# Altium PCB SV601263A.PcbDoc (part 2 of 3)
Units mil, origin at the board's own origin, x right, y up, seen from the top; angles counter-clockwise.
Board outline 4070 x 6530 mil, 6 copper layers (Top Layer, Signal Layer 1, Signal Layer 2, Signal Layer 3, Signal Layer 4, Bottom Layer), stack 60.36 mil thick; 305 components, 177 nets, 942 pads, 354 vias.
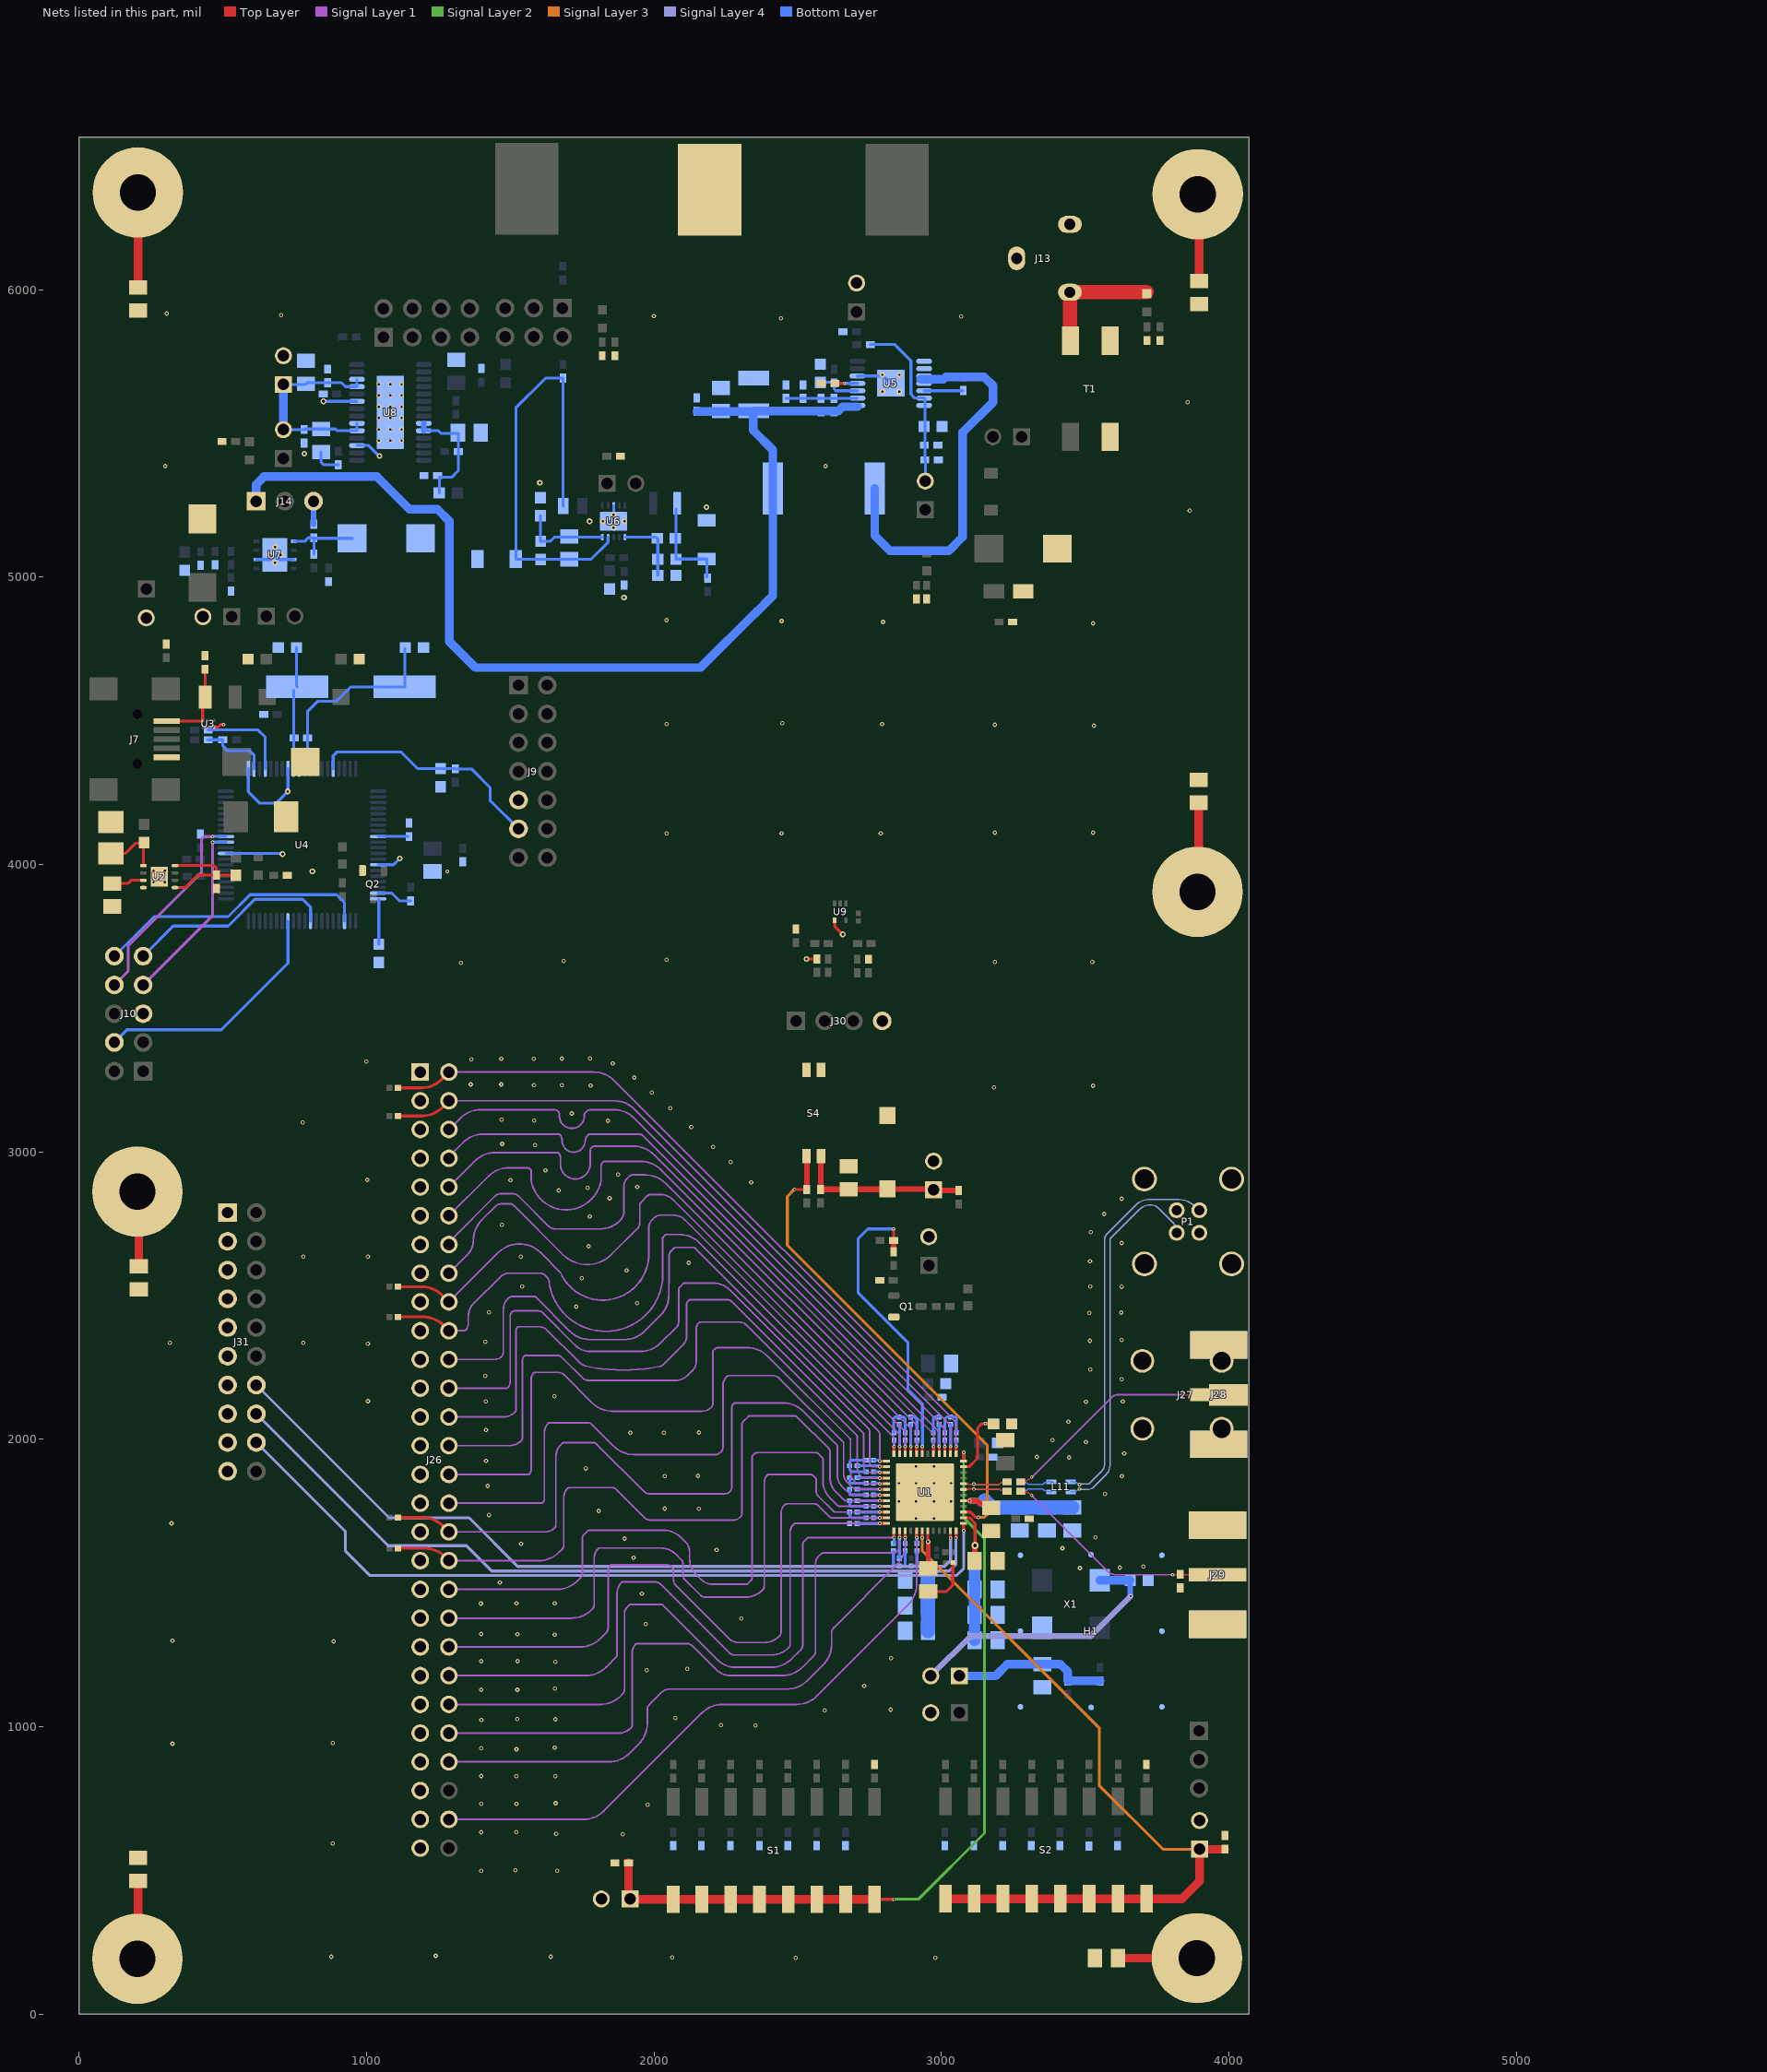
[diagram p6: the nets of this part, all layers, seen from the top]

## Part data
C1 C2 C18 C24 C25 C27 C28 C32 C34 C43 C46 C53 C73 C74 C77 C78 C83: "CAP, CERM, 0.1uF, 16V, +/-10%, X7R, 0402"
C3 C26 C52 C75 C79: "CAP, CERM, 10uF, 10V, +/-10%, X7R, 0805"
C4 C72 C76: "CAP, CERM, 4.7uF, 16V, +/-10%, X7R, 0805"
C5: "CAP, CERM, 0.01uF, 100V, +/-5%, X7R, 0603"
C6: library part GRM188R61C104KA01D, "CAP, CERM, 0.1 µF, 16 V, +/- 10%, X5R, 0603"
C7: "CAP, CERM, 0.1 µF, 16 V, +/- 10%, X5R, 0603"
C8 C9 C10 C11 C12 C13: "CAP, CERM, 4700 pF, 100 V, +/- 10%, X7R, 0805"
C14: "CAP, TA, 22uF, 20V, +/-20%, 0.7 ohm, SMD"
C15: "CAP, CERM, 1 µF, 6.3 V, +/- 20%, X5R, 0402"
C16: "CAP, TA, 2.2uF, 25V, +/-10%, 3.8 ohm, SMD"
C17: "CAP, CERM, 0.01uF, 100V, +/-10%, X7R, 0805"
C19 C21: "CAP, CERM, 20 pF, 100 V, +/- 5%, C0G/NP0, 0603"
C20: "CAP, CERM, 220 pF, 50 V, +/- 1%, C0G/NP0, 0603"
C22: "CAP, CERM, 200 pF, 50 V, +/- 5%, C0G/NP0, 0402"
C23: "CAP, CERM, 2200 pF, 50 V, +/- 10%, X7R, 0603"
C29: "CAP, CERM, 0.47uF, 16V, +/-10%, X7R, 0603"
C30 C31: "CAP, CERM, 10pF, 50V, +/-5%, C0G/NP0, 0402"
C33 C58: library part C1608X7R1C105K080AC, "CAP, CERM, 1 µF, 16 V, +/- 10%, X7R, 0603"
C35 C36 C37 C38 C39 C40 C41 C42 C47 C48 C49 C50 C56 C62: "CAP, CERM, 4.7 µF, 16 V, +/- 10%, X7R, AEC-Q200 Grade 1, 0805"
C44 C70 C71: "CAP, TA, 22uF, 25V, +/-20%, 0.7 ohm, SMD"
C45: "CAP, TA, 2.2uF, 25V, +/-10%, 6.3 ohm, SMD"
C51: "CAP, CERM, 47uF, 16V, +/-20%, X5R, 1210"
C54 C64: "CAP, CERM, 0.047 µF, 16 V, +/- 10%, X7R, 0402"
C55 C63: "CAP, CERM, 0.47 µF, 25 V, +/- 10%, X7R, 0603"
C57: "CAP, CERM, 3300pF, 50V, +/-10%, X7R, 0402"
C59 C68: "CAP, CERM, 10 µF, 25 V, +/- 20%, X5R, 0603"
C60: library part 06035A330JAT2A, "CAP, CERM, 33 pF, 50 V, +/- 5%, C0G/NP0, 0603"
C61 C66: "CAP, CERM, 22 µF, 35 V, +/- 20%, X5R, 1206_190"
C65: "CAP, CERM, 33 pF, 50 V, +/- 5%, C0G/NP0, 0603"
C67: library part C1005X7R1H104K050BB, "CAP, CERM, 0.1 µF, 50 V, +/- 10%, X7R, 0402"
C69: "CAP, CERM, 0.47 µF, 16 V, +/- 10%, X5R, 0402"
C80 C81: library part GCM155R71H104KE02D, "CAP, CERM, 0.1 µF, 50 V, +/- 10%, X7R, AEC-Q200 Grade 1, 0402"
C82: "CAP, CERM, 0.33 µF, 10 V, +/- 10%, X5R, 0402"
C84: "CAP, CERM, 0.15 µF, 10 V, +/- 10%, X5R, 0402"
C85 C86: "CAP, CERM, 4.7pF, 25V, +/-5%, C0G/NP0, 0402"
D1 D2 D3 D4 D5 D8: "LED, Green, SMD"
D6: "LED, Orange, SMD"
D7: "Diode, Zener, 7.5V, 550mW, SMB"
D9: "Diode, Schottky, 40V, 1A, SOD-123"
F1: "Fuse, 7 A, 24 V, SMD"
H1: "EMI SHIELD, 13.66 x 12.70 mm, SMT"
J1 J2 J3 J5 J6 J8 J11 J12 J15 J16 J18 J19 J20 J22 J32: "Header, 100mil, 2x1, Gold, TH"
J4 J14: "Header, 100mil, 3x1, Gold, TH"
J7: "Connector, Receptacle, Mini-USB Type B, R/A, Top Mount SMT"
J9: "Header, 100mil, 7x2, Tin, TH"
J10: "Header, 100mil, 5x2, Tin, TH"
J13: "Connector, DC Jack 2.1X5.5 mm, TH"
J17: "Header, 100mil, 3x2, Gold, TH"
J21: "Header, 100mil, 4x2, Gold, TH"
J23 J25: "Standard Banana Jack, Insulated, Red"
J24: "Standard Banana Jack, Insulated, Black"
J26: "Header, 100mil, 28x2, Gold, TH"
J27: "Connector, RF, 50 Ohm, R/A, TH"
J28 J29: "Connector, End launch SMA, 50 ohm, SMT"
J30: "Header (friction lock), 100mil, 4x1, Gold, TH"
J31: "Header, 100mil, 10x2, TH"
L1 L7 L9: "Ferrite Bead, 1000 ohm @ 100 MHz, 0.35 A, 0402"
L2: "Ferrite Bead, 60 ohm @ 100MHz, 0.8A, 0603"
L6: "Inductor, Shielded Drum Core, Ferrite, 4.7 µH, 4.2 A, 0.02 ohm, SMD"
L8: "Inductor, Shielded, Ferrite, 2.2 µH, 1.23 A, 0.084 ohm, SMD"
L10: "Inductor, Multilayer, Ferrite, 3.3 µH, 0.6 A, 0.143 ohm, SMD"
L11: "Coupled inductor, 0.28 A, 0.41 ohm, +/- 25%, SMD"
LBL?: library part THT-13-457-10, "Thermal Transfer Printable Labels, 1.250\" W x 0.250\" H - 10,000 per roll"
Logo1: library part TI_Logo, "Texas Instrument Corporate Signature"
Logo2: library part FCC_disclaimer, "FCC_disclaimer"
Logo?: library part Pb-Free
M1 M2 M3 M4 M5 M6: "TEST POINT.  No entry in BOM."
P1: "HSD Right Angle Plug for PCB, TH"
Q1 Q2: "MOSFET, N-CH, 50 V, 0.22 A, SOT-23"
R1 R8 R22 R30 R53 R56 R64 R94 R99 R105 R110 R113 R118 R119: "RES, 0 ohm, 5%, 0.063W, 0402"
R2 R9 R21 R29: "RES, 107k ohm, 1%, 0.063W, 0402"
R3 R10 R20 R28: "RES, 255k ohm, 1%, 0.063W, 0402"
R4 R11: "RES, 100k ohm, 1%, 0.1W, 0402"
R5 R12: "RES, 105k ohm, 1%, 0.063W, 0402"
R6 R13 R17 R25: "RES, 102k ohm, 1%, 0.063W, 0402"
R7 R14 R16 R24: "RES, 17.8k ohm, 1%, 0.063W, 0402"
R15 R23 R31 R32 R33 R93 R97 R100 R103 R107: "RES, 10.0 k, 1%, 0.063 W, 0402"
R18 R26: "RES, 75k ohm, 5%, 0.063W, 0402"
R19 R27: "RES, 140k ohm, 1%, 0.063W, 0402"
R34 R37 R39 R121 R122 R123 R124 R125 R126: "RES, 0, 5%, 0.05 W, 0201"
R35 R36 R38 R40 R41 R42 R43 R44 R45 R46 R47 R49 R50 R51 R52 R54 R55 R57 R58 R59 R60 R61 R62 R63 R65 R66 R67 R68: "RES, 49.9, 1%, 0.05 W, 0201"
R48 R115 R116: "RES, 4.7k ohm, 5%, 0.063W, 0402"
R69: "RES, 470 ohm, 5%, 0.063W, 0402"
R70 R71 R75 R76: "RES, 2.4 k, 5%, 0.063 W, 0402"
R72 R73: "RES, 220, 5%, 0.063 W, 0402"
R74 R77: "RES, 180, 5%, 0.063 W, 0402"
R78 R92 R109 R112: "RES, 100k ohm, 5%, 0.063W, 0402"
R79 R111 R114: "RES, 0, 5%, 0.1 W, 0603"
R80 R81: "RES, 33 ohm, 5%, 0.063W, 0402"
R82: "RES, 1.5 k, 5%, 0.063 W, 0402"
R83 R86: "RES, 33k ohm, 5%, 0.063W, 0402"
R84: "RES, 1.2 M, 5%, 0.1 W, 0603"
R85: library part CRCW04020000Z0ED, "RES, 0, 5%, 0.063 W, 0402"
R87: "RES, 200 ohm, 5%, 0.063W, 0402"
R88 R89: "RES, 0, 5%, 0.063 W, 0402"
R90: "RES, 124k ohm, 1%, 0.063W, 0402"
R91: "RES, 22.1k ohm, 1%, 0.063W, 0402"
R95 R108: "RES, 3.24k ohm, 1%, 0.063W, 0402"
R96: "RES, 806 k, 0.1%, 0.125 W, 0805"
R98 R104: "RES, 180 k, 0.1%, 0.1 W, 0603"
R101: library part ERJ-3EKF3603V, "RES, 360 k, 1%, 0.1 W, AEC-Q200 Grade 0, 0603"
R102: library part CRCW040210K0FKED, "RES, 10.0 k, 1%, 0.063 W, 0402"
R106: "RES, 29.4 k, 1%, 0.063 W, 0402"
R117: "RES, 49.9 ohm, 1%, 0.063W, 0402"
S1 S2: "Switch, Slide, SPST 8 poles, SMT"
S3 S5: "Switch, Normally open, 2.3N force, 200k operations, SMD"
S4: "Switch, SPST, 2 Pos, 25mA, 24VDC, SMD"
SH-J11 SH-J12 SH-J19 SH-J22: "Shunt, 100mil, Gold plated, Black"
T1: "Common Mode Filter for Power Line"
U1: "5 - 96 MHz 24-bit Color FPD-Link III Serializer with Bidirectional Control Channel, RHS0048A"
U2: "Single Output High PSRR LDO, 500 mA, Fixed 3.3 V Output, 2.7 to 6.5 V Input, with Low IQ, 8-pin SON (DRB), -40 to 125 degC, Green (RoHS & no Sb/Br)"
U3: "4-CHANNEL ESD-PROTECTION ARRAY FOR HIGH-SPEED DATA INTERFACES, DRY006A"
U4: "Mixed Signal MicroController, PN0080A"
U5: "4.5V to 18V Input, 2-A Synchronous Step-Down SWIFT™ Converter, PWP0014E"
U6: "2.25MHz 2x800mA Dual Step Down Converter In Small 3x3mm QFN Package, DRC0010J"
U7: "1A Low Dropout Adjustable Regulator, 8-pin LLP, Pb-Free"
U8: "Dual Output LDO, 1 A, Fixed 1.8, 3.3 V Output, 2.7 to 10 V Input, 28-pin HTSSOP (PWP), -40 to 125 degC, Green (RoHS & no Sb/Br)"
U9: "Low-Capacitance + / - 15 kV ESD-Protection Array for High-Speed Data Interfaces, 2 Channels, -40 to +85 degC, 5-pin SOT (DRL), Green (RoHS & no Sb/Br)"
X1: "OSC, 96 MHz, 3.3 Vdc, SMD"
Y1: "Crystal, 24.000MHz, 20pF, SMD"
ZZ1: library part AssemblyNote
ZZ2 ZZ3 ZZ4 ZZ5: library part AssemblyNoteLabel
ZZ6 ZZ7 ZZ8 ZZ9: library part "Assembly Note"

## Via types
v1: diameter 15, hole 7.5, Top Layer to Bottom Layer, 187 vias
v2: diameter 12, hole 6, Top Layer to Bottom Layer, 96 vias
v3: diameter 19.68, hole 7.87, Top Layer to Bottom Layer, 28 vias
v4: diameter 15.75, hole 7.87, Top Layer to Bottom Layer, 18 vias
v5: diameter 20, hole 10, Top Layer to Bottom Layer, 14 vias
v6: diameter 25, hole 12, Top Layer to Bottom Layer, 9 vias
v7: diameter 16, hole 8, Top Layer to Bottom Layer, 2 vias

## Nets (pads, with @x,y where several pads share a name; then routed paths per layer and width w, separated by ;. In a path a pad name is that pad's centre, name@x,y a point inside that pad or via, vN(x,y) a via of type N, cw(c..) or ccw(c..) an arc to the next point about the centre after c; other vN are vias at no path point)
5V_LDO: J14.3 R105.2 | length 79.4
  Bottom Layer w20: R105.2@816,5184.62 J14.3@816,5264
5V_SW: C30.2 C51.1 C52.1 C53.2 J14.1 L6.1 R90.1 U5.1 | length 3735.7
  Bottom Layer w30: J14.1@616,5264 616,5322 644,5350 1036,5350 1150,5236 1247,5236 1288,5195 1288,4776.37 1379.37,4685 2162,4685 2358,4881 ; C53.2@2149,5576.38 2345.46,5576.38 2345.46,5510.54 2413.83,5442.17 L6.1@2413.83,5308 2413.83,4934.83 2351,4872 ; C51.1@2347,5577.91 2641.54,5577.91 2656.58,5592.96 U5.1@2707.86,5592.96
12V_IN_B4JUMP: D1.2 J13.1 T1.2 | length 435.1
  Top Layer w50: T1.2@3449.1,5822.32 cw(c3454.18,5827.4) 3447,5827.4 J13.1@3447,5990.89 D1.2@3713,5990.89
CAPHS_12: C39.1 C40.1 C41.1 C42.1 U1.17 | length 466.3
  Top Layer w10: U1.17@3076.86,1786.47 v2(3098.53,1786.47)
  Top Layer w20: v2(3098.53,1786.47) 3123.53,1786.47 3133,1777 C42.1@3173,1777
  Bottom Layer w20: v2(3098.53,1786.47) 3151.53,1786.47
  Bottom Layer w50: 3151.53,1786.47 3175,1763 C41.1@3273,1763 C40.1@3367,1763 C39.1@3455,1763
CAPL12: C35.1 C36.1 C37.1 C38.1 U1.7 | length 447.1
  Top Layer w10: v7@2952.84,1644 U1.7@2952.84,1682.14
  Top Layer w15: C38.1@2954,1545 v7(2954,1644)
  Bottom Layer w15: C37.1@2954,1511 v7(2954,1644)
  Bottom Layer w50: C36.1@2954,1334 C35.1@2954,1422 C37.1@2954,1511
CAPP_12: C47.1 C48.1 C49.1 C50.1 U1.14 | length 507.2
  Top Layer w10: U1.14@3076.86,1727.42 3097.58,1727.42 3117,1708 v6(3117,1631)
  Top Layer w20: C50.1@3116,1577 v6@3116,1630
  Bottom Layer w20: 3116,1577 v6@3116,1630
  Bottom Layer w40: C47.1@3116,1301 3116,1577
CMF: C6.1 C7.1 U1.23 | length 257.4
  Top Layer w10: U1.23@3076.86,1904.58 3096.58,1904.58 3126,1934 3126,2040 3140,2054 C6.1@3181.5,2054
  Bottom Layer w10: v2(3153,2055) ccw(c3155.41,2057.41) 3155.41,2054 C7.1@3181.5,2054
DE: J26.54 R68.1 U1.5 | length 2179.8
  Top Layer w10: U1.5@2913.47,1682.14 2913.47,1659.27 ccw(c2915.27,1659.27) v2(2914,1658)
  Signal Layer 1 w6: J26.54@1287,678 1755.58,678 ccw(c1755.58,778) 1826.29,707.29 2167.71,1048.71 cw(c2238.42,978) 2238.42,1078 2496.58,1078 ccw(c2496.58,1178) 2567.29,1107.29 2884.71,1424.71 ccw(c2814,1495.42) 2914,1495.42 v2(2914,1658)
  Bottom Layer w10: v2(2914,1658) cw(c2911.59,1655.59) 2915,1655.59 R68.1@2915,1637.99
DIN0/R0: J26.2 R35.2 R121.2 U1.25 | length 2588.6
  Top Layer w10: R121.2@1109.96,3223 1190.58,3223 ccw(c1190.58,3323) 1261.29,3252.29 J26.2@1287,3278 ; U1.25@3051.27,1949.86 v2@3051.27,1974.73
  Signal Layer 1 w6: J26.2@1287,3278 1790.57,3278 cw(c1790.57,3178) 1861.28,3248.71 3041.11,2068.89 cw(c3017.22,2045) 3051,2045 v2(3051,1975)
  Bottom Layer w10: v2@3052,1976 R35.2@3052,1997.01
DIN1/R1: J26.4 R36.1 R122.2 U1.26 | length 2577.2
  Top Layer w10: R122.2@1109.96,3125 1192.58,3125 ccw(c1192.58,3225) 1263.29,3154.29 J26.4@1287,3178 ; U1.26@3031.58,1949.86 v2@3031.58,1974.58
  Signal Layer 1 w6: J26.4@1287,3178 1861.58,3178 cw(c1861.58,3078) 1932.29,3148.71 3021,2060 cw(c2994.44,2033.44) 3032,2033.44 v2(3032,1975)
  Bottom Layer w10: v2(3032,1975) R36.1@3032,2052.01
DIN2/R2: J26.6 R38.1 U1.27 | length 2388.1
  Top Layer w10: v2@3011.9,1974.9 U1.27@3011.9,1949.86 U1.27@3012,1949.96
  Signal Layer 1 w6: J26.6@1287,3078 1326.71,3117.71 cw(c1397.42,3047) 1397.42,3147 1652.51,3147 cw(c1652.51,3126.51) 1667,3141 cw(c1657.34,3131.34) 1671,3131.34 1671,3123 ccw(c1714.57,3125.65) 1758,3121.27 ; 1758,3122 1758,3129 cw(c1767.66,3129) 1760.83,3135.83 1766,3141 cw(c1780.49,3126.51) 1780.49,3147 1860.58,3147 cw(c1860.58,3047) 1931.29,3117.71 3004,2045 cw(c2984.69,2025.69) 3012,2025.69 v2(3012,1975)
  Bottom Layer w10: v2(3012,1975) R38.1@3012,1997.01
DIN3/R3: J26.8 R40.1 U1.28 | length 2396.4
  Top Layer w10: U1.28@2992.21,1949.86 v2@2992.21,1974.79
  Signal Layer 1 w6: J26.8@1287,2978 cw(c1301.49,2978) 1291.23,2988.23 1335.71,3032.71 cw(c1406.42,2962) 1406.42,3062 1670,3062 cw(c1670,3059.59) 1671.71,3061.29 cw(c1649.27,3038.86) 1681,3038.86 1681,3032 ; 1681,3034 ccw(c1720.57,3038.86) 1760,3033 cw(c1796.21,3033) 1770.61,3058.61 1773,3061 cw(c1775.41,3058.59) 1775.41,3062 1950.34,3062 cw(c1950.34,3048.34) 1960,3058 2987,2031 cw(c2974.93,2018.93) 2992,2018.93 v2(2992,1975)
  Bottom Layer w10: v2(2992,1975) R40.1@2992,2052.01
DIN4/R4: J26.10 R41.1 U1.29 | length 2379
  Top Layer w10: U1.29@2972.53,1949.86 v2@2972.53,1974.53
  Signal Layer 1 w6: J26.10@1287,2878 1377.71,2968.71 cw(c1448.42,2898) 1448.42,2998 1667,2998 cw(c1647.69,2978.69) 1675,2978.69 1675,2953 ccw(c1726.5,2957.71) 1778,2953 1778,3002 cw(c1797.31,3002) 1783.66,3015.66 1784.88,3016.88 cw(c1790,3011.76) 1790,3019 cw(c1792.41,3016.59) 1792.41,3020 1929.58,3020 cw(c1929.58,2920) 2000.29,2990.71 2967,2024 cw(c2952.51,2009.51) 2973,2009.51 v2(2973,1975)
  Bottom Layer w10: v2@2972,1976 R41.1@2972,1997.01
DIN5/R5: J26.12 R42.1 U1.32 | length 2387.4
  Top Layer w10: U1.32@2913.47,1949.86 v2@2913.47,1974.47
  Signal Layer 1 w6: J26.12@1287,2778 1424.71,2915.71 cw(c1495.42,2845) 1495.42,2945 1556.51,2945 cw(c1556.51,2924.51) 1571,2939 cw(c1566.17,2934.17) 1573,2934.17 1573,2900.41 ccw(c1694.5,2921.72) 1816,2900.41 1816,2947.27 cw(c1841.9,2947.27) 1823.59,2965.59 cw(c1827,2962.17) 1827,2967 1954.58,2967 cw(c1954.58,2867) 2025.29,2937.71 2911,2052 cw(c2903.76,2044.76) 2914,2044.76 v2(2914,1975)
  Bottom Layer w10: v2@2915,1976 R42.1@2915,1997.01
DIN6/R6: J26.14 R43.1 U1.33 | length 2396.1
  Top Layer w10: U1.33@2893.79,1949.86 v2@2893.79,1974.79
  Signal Layer 1 w6: J26.14@1287,2678 cw(c1306.31,2678) 1292.66,2691.66 1448,2847 cw(c1467.31,2827.69) 1467.31,2855 1504,2855 cw(c1504,2813.96) 1533.02,2842.98 1635.51,2740.49 ccw(c1656,2760.97) 1656,2732 1811.58,2732 ccw(c1811.58,2832) 1882.29,2761.29 ccw(c1849.19,2794.39) 1896,2794.39 1896,2883 cw(c1929.8,2883) 1905.9,2906.9 1914.76,2915.76 cw(c1925,2905.51) 1925,2920 1969.58,2920 cw(c1969.58,2820) 2040.29,2890.71 2890.46,2040.54 cw(c2881.93,2032) 2894,2032 v2(2894,1975)
  Bottom Layer w10: R43.1@2893,2052.01 2893.27,2051.74 v2@2893.27,1975.73
DIN7/R7: J26.16 R44.1 U1.34 | length 2378.8
  Top Layer w10: U1.34@2874.1,1949.86 v2@2874.1,1974.9
  Signal Layer 1 w6: J26.16@1287,2578 1351.08,2642.08 ccw(c1300.59,2692.58) 1372,2692.58 cw(c1472,2692.58) 1401.29,2763.29 1448.1,2810.1 cw(c1472,2786.2) 1472,2820 1497,2820 cw(c1497,2798.27) 1512.36,2813.64 1683,2643 ccw(c1767.5,2727.5) 1852,2643 1942.51,2733.51 ccw(c1922.03,2754) 1951,2754 1951,2815 cw(c1965.49,2815) 1955.23,2825.23 1977,2847 cw(c1989.07,2834.93) 1989.07,2852 2021,2852 cw(c2021,2784.4) 2068.8,2832.2 2871.17,2029.83 cw(c2864.32,2022.99) 2874,2022.99 v2(2874,1975)
  Bottom Layer w10: v2(2874,1975) R44.1@2874,1997.01
DIN8/G0: J26.18 R45.1 R123.2 U1.35 | length 2580.9
  Top Layer w10: R123.2@1109.96,2531 1192.58,2531 cw(c1192.58,2431) 1263.29,2501.71 J26.18@1287,2478 ; U1.35@2854.42,1949.86 v2@2854.42,1974.42
  Signal Layer 1 w6: J26.18@1287,2478 1458.6,2649.6 cw(c1532,2576.21) 1605.4,2649.6 1675,2580 ccw(c1821.82,2644.81) 1982,2635 1982,2735 cw(c2023.04,2735) 1994.02,2764.02 2002,2772 cw(c2021.31,2752.69) 2021.31,2780 2068,2780 cw(c2068,2724.47) 2107.26,2763.74 2850.05,2020.95 cw(c2838.1,2009) 2855,2009 v2(2855,1975)
  Bottom Layer w10: v2@2854.73,1975.27 2854.73,2051.74 R45.1@2855,2052.01
DIN9/G1: J26.20 R46.1 R124.2 U1.36 | length 2590.4
  Top Layer w10: R124.2@1109.96,2426 1197.58,2426 cw(c1197.58,2326) 1268.29,2396.71 J26.20@1287,2378 ; U1.36@2834.73,1949.86 v2@2834.73,1974.73
  Signal Layer 1 w6: J26.20@1304.07,2385.07 cw(c1287,2402.14) J26.20@1287,2378 1338.76,2378 ccw(c1338.76,2388.24) 1346,2381 ccw(c1326.69,2400.31) 1354,2400.31 1354,2426 cw(c1421.6,2426) 1373.8,2473.8 1465,2564 cw(c1497.77,2532.92) 1495,2578 1605,2578 cw(c1605,2556.27) 1620.36,2571.64 1628,2564 cw(c1607.48,2543.48) 1636.5,2543.48 1636.5,2537.6 ccw(c1831.95,2574.79) 2030,2555.79 2030,2697 cw(c2042.07,2697) 2033.54,2705.54 2038.88,2710.88 cw(c2044,2705.76) 2044,2713 2087.58,2713 cw(c2087.58,2613) 2158.29,2683.71 2832,2010 cw(c2824.76,2002.76) 2835,2002.76 v2(2835,1975)
  Bottom Layer w10: v2(2835,1975) R46.1@2835,1997.01
DIN10/G2: J26.22 R47.1 U1.37 | length 2389.6
  Top Layer w10: v2@2786.27,1924.27 U1.37@2809.14,1924.27
  Signal Layer 1 w6: J26.22@1287,2278 1447.27,2278 ccw(c1447.27,2308.73) 1469,2287 ccw(c1452.1,2303.9) 1476,2303.9 1476,2452 cw(c1526.7,2452) 1490.85,2487.85 1496,2493 cw(c1505.66,2483.34) 1505.66,2497 1583,2497 cw(c1583,2487.34) 1589.83,2494.17 1707.71,2376.29 ccw(c1778.42,2447) 1778.42,2347 1896.58,2347 ccw(c1896.58,2447) 1967.29,2376.29 2022.71,2431.71 ccw(c1952,2502.42) 2052,2502.42 2052,2543 ccw(c2049.59,2545.41) 2053,2545.41 2053,2640 cw(c2074.73,2640) 2059.36,2655.36 2066,2662 cw(c2080.49,2647.51) 2080.49,2668 2137,2668 cw(c2137,2658.34) 2143.83,2665.17 2780,2029 cw(c2765.51,2014.51) 2786,2014.51 v2(2786,1924)
  Bottom Layer w10: R47.1@2763.99,1928 2776.34,1928 cw(c2776.34,1914.34) v2(2786,1924)
DIN11/G3: J26.24 R49.1 U1.38 | length 2402
  Top Layer w10: v2(2786,1905) ccw(c2787.01,1906.01) 2787.01,1904.58 U1.38@2809.14,1904.58
  Signal Layer 1 w6: J26.24@1287,2178 1488.59,2178 ccw(c1488.59,2181.41) 1491,2179 ccw(c1469.27,2200.73) 1500,2200.73 1500,2428.51 cw(c1520.49,2428.51) 1506,2443 cw(c1515.66,2433.34) 1515.66,2447 1598,2447 cw(c1598,2425.27) 1613.36,2440.64 1727,2327 ccw(c1777.7,2377.7) 1777.7,2306 1952.58,2306 ccw(c1952.58,2406) 2023.29,2335.29 2079,2391 ccw(c2062.1,2407.9) 2086,2407.9 2086,2522 cw(c2095.66,2522) 2088.83,2528.83 2102,2542 cw(c2106.83,2537.17) 2106.83,2544 2205,2544 cw(c2205,2459.5) 2264.75,2519.25 2746,2038 cw(c2736.34,2028.34) 2750,2028.34 2750,1921.07 ccw(c2767.07,1921.07) 2755,1909 ccw(c2764.66,1918.66) 2764.66,1905 v2(2786,1905)
  Bottom Layer w10: R49.1@2706.99,1908 2778.76,1908 cw(c2778.76,1897.76) v2@2781,1907.75
DIN12/G4: J26.26 R50.1 U1.39 | length 2384.7
  Top Layer w10: v2@2786.1,1884.9 U1.39@2809.14,1884.9
  Signal Layer 1 w6: J26.26@1287,2078 1475.96,2078 ccw(c1475.96,2136.04) 1517,2095 ccw(c1509.76,2102.24) 1520,2102.24 1520,2377.93 cw(c1537.07,2377.93) 1525,2390 cw(c1529.83,2385.17) 1529.83,2392 1602,2392 cw(c1602,2358.2) 1625.9,2382.1 1738.5,2269.5 ccw(c1779.33,2310.62) 1767,2254 ccw(c1893.1,2859.06) 2019.2,2254 ccw(c2019.2,2270.41) 2030.81,2258.81 2101,2329 ccw(c2069.62,2360.38) 2114,2360.38 2114,2471 cw(c2126.07,2471) 2117.54,2479.54 2122,2484 cw(c2126.83,2479.17) 2126.83,2486 2256,2486 cw(c2256,2466.69) 2269.66,2480.34 2729,2021 cw(c2726.59,2018.59) 2730,2018.59 2730,1908 ccw(c2758.95,1908) 2738.48,1887.53 2738.89,1887.12 ccw(c2744,1892.22) 2744,1885 v2(2786,1885)
  Bottom Layer w10: R50.1@2763.99,1888 2778.76,1888 cw(c2778.76,1877.76) v2(2786,1885)
DIN13/G5: J26.28 R51.1 U1.40 | length 2385
  Top Layer w10: v2@2786.21,1865.21 U1.40@2809.14,1865.21
  Signal Layer 1 w6: J26.28@1287,1978 1496.96,1978 ccw(c1496.96,2036.04) 1538,1995 ccw(c1525.93,2007.07) 1543,2007.07 1543,2275.51 cw(c1563.49,2275.51) 1549,2290 cw(c1553.83,2285.17) 1553.83,2292 1665,2292 cw(c1665,2273.31) 1678.21,2286.53 1685.36,2279.38 1754,2212 ccw(c1770.9,2228.9) 1770.9,2205 2072,2205 ccw(c2072,2272.6) 2119.8,2224.8 2134,2239 ccw(c2102.62,2270.38) 2147,2270.38 2147,2384 cw(c2175.97,2384) 2155.49,2404.49 2156,2405 cw(c2163.24,2397.76) 2163.24,2408 2299,2408 cw(c2299,2379.03) 2319.49,2399.51 2706,2013 cw(c2703.59,2010.59) 2707,2010.59 2707,1905.21 ccw(c2758.21,1905.21) 2722,1869 ccw(c2731.66,1878.66) 2731.66,1865 v2(2786,1865)
  Bottom Layer w10: R51.1@2706.99,1867 2781.17,1867 cw(c2781.17,1860.17) v2(2786,1865)
DIN14/G6: J26.30 R52.1 U1.41 | length 2403.5
  Top Layer w10: v2(2786,1845) cw(c2787.27,1843.73) 2787.27,1845.53 U1.41@2809.14,1845.53
  Signal Layer 1 w6: J26.30@1287,1878 1563.59,1878 ccw(c1563.59,1881.41) 1566,1879 ccw(c1549.1,1895.9) 1573,1895.9 1573,2210.69 cw(c1600.31,2210.69) 1581,2230 cw(c1588.24,2222.76) 1588.24,2233 1667,2233 cw(c1667,2204.03) 1687.49,2224.51 1784.71,2127.29 ccw(c1855.42,2198) 1855.42,2098 2167.62,2098 ccw(c2167.62,2142.38) 2199,2111 ccw(c2184.51,2125.49) 2205,2125.49 2205,2306 cw(c2209.83,2306) 2206.41,2309.41 2212,2315 cw(c2221.66,2305.34) 2221.66,2319 2324.58,2319 cw(c2324.58,2219) 2395.29,2289.71 2682,2003 cw(c2677.17,1998.17) 2684,1998.17 2684,1884 ccw(c2722.63,1884) 2695.31,1856.69 2703,1849 ccw(c2712.66,1858.66) 2712.66,1845 v2(2786,1845)
  Bottom Layer w10: R52.1@2763.99,1847 2781.17,1847 cw(c2781.17,1840.17) v2(2786,1845)
DIN15/G7: J26.32 R54.1 U1.42 | length 2389.1
  Top Layer w10: v2@2786.16,1825.84 U1.42@2809.14,1825.84
  Signal Layer 1 w6: J26.32@1287,1778 1609.17,1778 ccw(c1609.17,1784.83) 1614,1780 ccw(c1601.93,1792.07) 1619,1792.07 1619,2023.2 cw(c1666.8,2023.2) 1633,2057 cw(c1635.41,2054.59) 1635.41,2058 1768,2058 cw(c1768,2033.86) 1785.07,2050.93 1860,1976 ccw(c1930.01,2046.01) 1930.01,1947 2211.27,1947 ccw(c2211.27,1977.73) 2233,1956 ccw(c2216.1,1972.9) 2240,1972.9 2240,2186.62 cw(c2284.38,2186.62) 2253,2218 cw(c2262.66,2208.34) 2262.66,2222 2412,2222 cw(c2412,2185.79) 2437.61,2211.39 2657,1992 cw(c2649.76,1984.76) 2660,1984.76 2660,1880 ccw(c2701.04,1880) 2672.02,1850.98 2686,1837 ccw(c2712.56,1863.56) 2712.56,1826 v2(2786,1826)
  Bottom Layer w10: R54.1@2706.99,1827 2783.59,1827 cw(c2783.59,1823.59) v2(2786,1826)
DIN16/B0: J26.34 R55.1 R125.2 U1.43 | length 2589
  Top Layer w10: R125.2@1109.96,1728 1195.58,1728 cw(c1195.58,1628) 1266.29,1698.71 J26.34@1287,1678 ; v2@2786.16,1806.16 U1.43@2809.14,1806.16
  Signal Layer 1 w6: J26.34@1287,1678 1621.2,1678 ccw(c1621.2,1725.8) 1655,1692 ccw(c1645.34,1701.66) 1659,1701.66 1659,1941 cw(c1714.53,1941) 1675.26,1980.26 1682,1987 cw(c1684.41,1984.59) 1684.41,1988 1792,1988 cw(c1792,1978.34) 1798.83,1985.17 1967,1817 ccw(c1981.49,1831.49) 1981.49,1811 2247.1,1811 ccw(c2247.1,1834.9) 2264,1818 ccw(c2247.1,1834.9) 2271,1834.9 2271,2112 cw(c2285.49,2112) 2275.23,2122.23 2277,2124 cw(c2284.24,2116.76) 2284.24,2127 2448.58,2127 cw(c2448.58,2027) 2519.29,2097.71 2637,1980 cw(c2634.59,1977.59) 2638,1977.59 2638,1875 ccw(c2691.11,1875) 2653.55,1837.45 2682,1809 ccw(c2689.24,1816.24) 2689.24,1806 v2(2786,1806)
  Bottom Layer w10: R55.1@2763.99,1807 2783.59,1807 cw(c2783.59,1803.59) v2(2786,1806)
DIN17/B1: J26.36 R57.1 R126.2 U1.44 | length 2573.9
  Top Layer w10: R126.2@1109.96,1621 1202.58,1621 cw(c1202.58,1521) 1273.29,1591.71 J26.36@1287,1578 ; v2(2786,1787) ccw(c2787.27,1788.27) 2787.27,1786.47 U1.44@2809.14,1786.47
  Signal Layer 1 w6: J26.36@1287,1578 1599.58,1578 ccw(c1599.58,1678) 1670.29,1607.29 1680,1617 ccw(c1665.51,1631.49) 1686,1631.49 1686,1797.62 cw(c1730.38,1797.62) 1699,1829 cw(c1706.24,1821.76) 1706.24,1832 1855,1832 cw(c1855,1812.69) 1868.66,1826.34 1967,1728 ccw(c1988.73,1749.73) 1988.73,1719 2274.44,1719 ccw(c2274.44,1756.56) 2301,1730 ccw(c2288.93,1742.07) 2306,1742.07 2306,2051 cw(c2320.49,2051) 2310.23,2061.23 2329,2080 cw(c2333.83,2075.17) 2333.83,2082 2486,2082 cw(c2486,2062.69) 2499.66,2076.34 2608,1968 cw(c2598.34,1958.34) 2612,1958.34 2612,1869 ccw(c2686.84,1869) 2633.92,1816.08 2660,1790 ccw(c2667.24,1797.24) 2667.24,1787 v2(2786,1787)
  Bottom Layer w10: R57.1@2706.99,1787 v2(2786,1787)
DIN18/B2: J26.38 R58.1 U1.45 | length 2392.6
  Top Layer w10: v2@2786.21,1766.79 U1.45@2809.14,1766.79
  Signal Layer 1 w6: J26.38@1287,1478 1662.58,1478 ccw(c1662.58,1578) 1733.29,1507.29 1745,1519 ccw(c1730.51,1533.49) 1751,1533.49 1751,1655 cw(c1770.31,1655) 1756.66,1668.66 1770,1682 cw(c1774.83,1677.17) 1774.83,1684 2032,1684 cw(c2032,1594.67) 2095.16,1657.84 2110,1643 cw(c2076.2,1609.2) 2124,1609.2 2124,1584 ccw(c2198.84,1584) 2145.92,1531.08 2165,1512 ccw(c2203.63,1550.63) 2203.63,1496 2322.17,1496 ccw(c2322.17,1502.83) 2326.99,1497.99 2338,1509 ccw(c2330.76,1516.24) 2341,1516.24 2341,1933.51 cw(c2361.49,1933.51) 2347,1948 cw(c2361.49,1933.51) 2361.49,1954 2563,1954 cw(c2563,1941.93) 2571.54,1950.46 2585,1937 cw(c2577.76,1929.76) 2588,1929.76 2588,1853 ccw(c2665.25,1853) 2610.63,1798.37 2638,1771 ccw(c2647.66,1780.66) 2647.66,1767 v2(2786,1767)
  Bottom Layer w10: R58.1@2763.99,1767 v2(2786,1767)
DIN19/B3: J26.40 R59.1 U1.46 | length 2383.4
  Top Layer w10: v2@2786.1,1747.1 U1.46@2809.14,1747.1
  Signal Layer 1 w6: J26.40@1287,1378 1712.58,1378 ccw(c1712.58,1478) 1783.29,1407.29 1787,1411 ccw(c1774.93,1423.07) 1792,1423.07 1792,1586.2 cw(c1839.8,1586.2) 1806,1620 cw(c1810.83,1615.17) 1810.83,1622 2023,1622 cw(c2023,1544.75) 2077.63,1599.37 2096,1581 cw(c2083.93,1568.93) 2101,1568.93 2101,1525 ccw(c2115.49,1525) 2105.23,1514.77 2164,1456 ccw(c2176.07,1468.07) 2176.07,1451 2319.06,1451 ccw(c2319.06,1532.94) 2377,1475 ccw(c2360.1,1491.9) 2384,1491.9 2384,1850.86 cw(c2418.14,1850.86) 2394,1875 cw(c2401.24,1867.76) 2401.24,1878 2544,1878 cw(c2544,1863.51) 2554.23,1873.77 2562,1866 cw(c2554.76,1858.76) 2565,1858.76 2565,1842 ccw(c2567.41,1839.59) 2564,1839.59 2564,1822 ccw(c2592.97,1822) 2572.49,1801.51 2624,1750 ccw(c2631.24,1757.24) 2631.24,1747 v2(2786,1747)
  Bottom Layer w10: R59.1@2706.99,1747 v2(2786,1747)
DIN20/B4: J26.42 R60.1 U1.47 | length 2391.1
  Top Layer w10: v2(2786,1727) cw(c2787.01,1725.99) 2787.01,1727.42 U1.47@2809.14,1727.42
  Signal Layer 1 w6: J26.42@1287,1278 1743.58,1278 ccw(c1743.58,1378) 1814.29,1307.29 1832,1325 ccw(c1810.27,1346.73) 1841,1346.73 1841,1545.1 cw(c1864.9,1545.1) 1848,1562 cw(c1850.41,1559.59) 1850.41,1563 2048,1563 cw(c2048,1548.51) 2058.23,1558.77 2066,1551 cw(c2061.17,1546.17) 2068,1546.17 2068,1512 ccw(c2096.97,1512) 2076.49,1491.51 2150,1418 2261.56,1306.43 ccw(c2294,1338.87) 2294,1293 2384.3,1293 ccw(c2384.3,1364.7) 2435,1314 ccw(c2415.69,1333.31) 2443,1333.31 2443,1746.2 cw(c2478.73,1746.2) 2453.46,1771.46 cw(c2462,1762.93) 2462,1775 cw(c2464.41,1772.59) 2464.41,1776 2558,1776 cw(c2558,1759.1) 2569.94,1771.06 2610,1731 ccw(c2619.66,1740.66) 2619.66,1727 v2(2786,1727)
  Bottom Layer w10: R60.1@2763.99,1727 v2(2786,1727)
DIN21/B5: J26.44 R61.1 U1.48 | length 2398.6
  Top Layer w10: v2@2786.27,1707.73 U1.48@2809.14,1707.73
  Signal Layer 1 w6: J26.44@1287,1178 1762.58,1178 ccw(c1762.58,1278) 1833.29,1207.29 1872,1246 1872,1464.37 cw(c1926.63,1464.37) 1888,1503 cw(c1890.41,1500.59) 1890.41,1504 2004,1504 cw(c2004,1477.44) 2022.78,1496.22 2058,1461 2265,1255 ccw(c2277.07,1267.07) 2277.07,1250 2408.64,1250 ccw(c2408.64,1335.36) 2469,1275 ccw(c2456.93,1287.07) 2474,1287.07 2474,1677.44 cw(c2511.56,1677.44) 2485,1704 cw(c2494.66,1694.34) 2494.66,1708 v2(2786,1708)
  Bottom Layer w10: R61.1@2706.99,1707 2783.59,1707 ccw(c2783.59,1710.41) v2(2786,1708)
DIN22/B6: J26.46 R62.1 U1.1 | length 2378.7
  Top Layer w10: v2@2834.73,1658.27 U1.1@2834.73,1682.14
  Signal Layer 1 w6: J26.46@1287,1078 1813.58,1078 ccw(c1813.58,1178) 1884.29,1107.29 1890,1113 ccw(c1870.69,1132.31) 1898,1132.31 1898,1397.51 cw(c1918.49,1397.51) 1904,1412 cw(c1906.41,1412) 1904.71,1413.71 1916,1425 cw(c1918.41,1422.59) 1918.41,1426 2026,1426 cw(c2026,1418.76) 2031.12,1423.88 2224,1231 ccw(c2281.94,1288.94) 2281.94,1207 2408.58,1207 ccw(c2408.58,1307) 2479.29,1236.29 2510,1267 ccw(c2490.69,1286.31) 2518,1286.31 2518,1635 cw(c2532.49,1635) 2522.23,1645.23 2533,1656 cw(c2537.83,1651.17) 2537.83,1658 v2(2835,1658)
  Bottom Layer w10: R62.1@2835,1637.99 v2(2835,1658)
DIN23/B7: J26.48 R63.1 U1.2 | length 2396.5
  Top Layer w10: U1.2@2854.42,1682.14 2854.42,1659.41 ccw(c2856.41,1659.41) v2(2855,1658)
  Signal Layer 1 w6: J26.48@1287,978 1876.54,978 ccw(c1876.54,1039.46) 1920,996 ccw(c1910.34,1005.66) 1924,1005.66 1924,1256.62 cw(c1968.38,1256.62) 1937,1288 cw(c1939.41,1285.59) 1939.41,1289 2118,1289 cw(c2118,1269.69) 2131.66,1283.34 2215,1200 ccw(c2268.11,1253.11) 2268.11,1178 2445.58,1178 ccw(c2445.58,1278) 2516.29,1207.29 2557,1248 ccw(c2544.93,1260.07) 2562,1260.07 2562,1569.59 cw(c2565.41,1569.59) 2563,1572 cw(c2589.56,1572) 2570.78,1590.78 2581,1601 cw(c2590.66,1591.34) 2590.66,1605 2826.86,1605 ccw(c2826.86,1639.14) 2851,1615 ccw(c2841.34,1624.66) 2855,1624.66 v2(2855,1658)
  Bottom Layer w10: R63.1@2854,1585.99 2854,1655.59 cw(c2857.41,1655.59) v2(2855,1658)
DM: R80.1 U4.64 | length 319
  Bottom Layer w10: R80.1@449.62,4468 623,4468 648.05,4442.95 U4.64@648.05,4332.76
DOUT0SMA_N: C81.1 L11.2 | length 112
  Bottom Layer w5.5: C81.1@3275.62,1819 3281.75,1819 ccw(c3281.75,1848.87) 3302.87,1827.75 3351.6,1827.75 ccw(c3376.87,1853.02) 3376.87,1817.28 L11.2@3382.54,1817.28
DOUT0SMA_P: C80.1 L11.3 | length 111.8
  Bottom Layer w5.5: C80.1@3275.62,1852 3281.75,1852 cw(c3281.75,1822.13) 3302.87,1843.25 3352.6,1843.25 cw(c3375.46,1820.4) 3375.46,1852.72 L11.3@3382.54,1852.72
DOUT_N: C81.2 C84.2 U1.19 | length 272.8
  Top Layer w5.5: U1.19@3076.86,1825.84 3088.46,1825.84 ccw(c3088.46,1832.99) 3093.51,1827.94 3110.74,1827.94 cw(c3110.74,1824.74) v2(3113,1827) cw(c3114.81,1825.19) 3114.81,1827.75 3201.13,1827.75 ccw(c3222.25,1848.87) 3222.25,1819 C84.2@3228.38,1819
  Bottom Layer w5.5: v2(3113,1827) cw(c3114.81,1825.19) 3114.81,1827.75 3201.13,1827.75 ccw(c3222.25,1848.87) 3222.25,1819 C81.2@3228.38,1819
DOUT_P: C80.2 C82.2 U1.20 | length 272.7
  Top Layer w5.5: U1.20@3076.86,1845.53 3088.46,1845.53 cw(c3088.46,1838.38) 3093.51,1843.44 3111.64,1843.44 ccw(c3111.64,1845.36) v2(3113,1844) ccw(c3114.81,1845.81) 3114.81,1843.25 3201.13,1843.25 cw(c3222.25,1822.13) 3222.25,1852 C82.2@3228.38,1852
  Bottom Layer w5.5: v2(3113,1844) ccw(c3114.81,1845.81) 3114.81,1843.25 3201.13,1843.25 cw(c3222.25,1822.13) 3222.25,1852 C80.2@3228.38,1852
DOUTSMA0_N: C84.1 J29.1 R117.2 | length 797.2
  Top Layer w5.5: C84.1@3280.2,1819 cw(c3280.2,1771.2) v2(3314,1805) ; v2(3804,1529) J29.1@3961,1529
  Signal Layer 1 w6: v2(3314,1805) 3578.76,1540.24 ccw(c3605.89,1567.37) 3605.89,1529 v2(3804,1529)
DOUTSMA0_P: C82.1 J27.1 J28.1 | length 809.7
  Top Layer w5.5: C82.1@3275.62,1852 ccw(c3275.62,1903.61) 3312.12,1867.12 v2(3314,1869) ; v2(3839,2155) 3962.59,2155 ccw(c3962.59,2158.41) J28.1@3965,2156
  Signal Layer 1 w6: v2@3315.71,1869.71 3592.93,2146.93 cw(c3612.42,2127.43) 3612.42,2155 v2(3839,2155)
DP: R81.1 R82.2 U4.62 | length 242
  Bottom Layer w10: R81.1@449.62,4434 R82.2@500.38,4434 500.38,4412.62 517,4396 594,4396 608.68,4381.32 U4.62@608.68,4332.76
FSEL: R32.1 S4.3 U1.15 | length 1681.7
  Top Layer w10: v2(2488.62,2869.62) R32.1@2532,2869.62 ; U1.15@3076.86,1747.1 3100.53,1747.1 3118.63,1729 v2(3129,1729)
  Top Layer w20: R32.1@2532,2869.62 S4.3@2532,2984
  Signal Layer 3 w10: v2(2488.62,2869.62) 2464,2845 2464,2675 3160,1979 3160,1739 3150,1729 v2(3129,1729)
GND: C1.2 C2.2 C3.2 C4.2 C5.2 C6.2 C7.2 C8.2 C9.2 C10.2 C11.2 C12.2 C13.2 C14.2 C15.2 C16.2 C17.2 C18.1 C19.1 C20.1 C21.1 C22.2 C23.1 C24.2 C25.2 C26.2 C27.1 C28.2 C29.2 C31.1 C32.2 C33.2 C34.2 C35.2 C36.2 C37.2 C38.2 C39.2 C40.2 C41.2 C42.2 C43.1 C44.2 C45.2 C47.2 C48.2 C49.2 C50.2 C51.2 C52.2 C53.1 C54.2 C55.2 C56.2 C57.2 C58.2 C59.1 C61.2 C62.2 C63.2 C64.2 C66.2 C67.2 C68.2 C69.2 C70.2 C71.2 C72.1 C73.2 C74.1 C75.2 C76.1 C77.2 C78.1 C79.2 C83.1 C85.2 C86.2 D7.2 H1.1 J1.2 J2.2 J3.2 J6.2 J7.5 J9.9 J10.5 J13.2 J13.3 J15.2 J18.2 J19.2 J20.2 J24.1 J26.1 J26.3 J26.5 J26.7 J26.9 J26.11 J26.13 J26.15 J26.17 J26.19 J26.21 J26.23 J26.25 J26.27 J26.29 J26.31 J26.33 J26.35 J26.37 J26.39 J26.41 J26.43 J26.45 J26.47 J26.49 J26.51 J26.53 J26.55 J27.2 J27.3 J27.4 J27.5 J28.2 J28.3 J28.4 J28.5 J29.2 J29.3 J29.4 J29.5 J30.4 J31.1 J31.3 J31.5 J31.7 J31.9 J31.11 J31.13 J31.15 J31.17 J31.19 J32.2 P1.2 P1.4 P1.MH Q1.2 Q2.2 R15.1 R16.1 R17.1 R18.1 R19.1 R20.1 R21.1 R22.1 R23.1 R24.1 R25.1 R26.1 R27.1 R28.1 R29.1 R30.1 R35.1 R36.2 R38.2 R40.2 R41.2 R42.2 R43.2 R44.2 R45.2 R46.2 R47.2 R49.2 R50.2 R51.2 R52.2 R54.2 R55.2 R56.2 R57.2 R58.2 R59.2 R60.2 R61.2 R62.2 R63.2 R65.2 R66.2 R67.2 R68.2 R70.1 R71.1 R72.1 R73.1 R74.1 R75.1 R76.1 R77.1 R78.1 R83.1 R84.1 R91.2 R95.1 R97.1 R98.1 R102.1 R104.1 R107.1 R108.1 R110.1 R113.1 R117.1 S3.2 S4.1 S4.2 T1.1 T1.4 U1.49 U2.4 U2.9 U3.3 U4.14 U4.19 U4.49 U4.61 U4.68 U5.5 U5.8 U5.9 U5.15 U6.8 U6.11 U7.2 U7.7 U7.9 U8.3 U8.9 U8.29 U9.4 X1.2 | length 2796.9
  Top Layer w10: U3.3@469.68,4478.19 484.19,4478.19 493,4487 v2(503,4487) ; v5@2531.62,3671.62 C85.2@2567,3671.62 ; U9.4@2628.32,3805.47 2628.32,3785.69 v5(2657,3757) ; C38.2@2954,1471 3018.21,1471 3039.99,1492.78 R65.2@3039.99,1571
  Bottom Layer w10: U4.49@511.24,4038.47 v5@705.53,4038.47 ; U4.61@588.99,4332.76 588.99,4253.01 629,4213 685.79,4213 726.79,4254 U4.68@726.79,4332.76 ; U7.2@617.04,5061.25 666.25,5061.25 U7.9@682,5077 697.75,5061.25 U7.7@746.96,5061.25 ; C72.1@842,5435 842,5400 851.62,5390.38 R110.1@902,5390.38 ; v5(850.61,5611.39) U8.9@966.86,5611.39 ; U8.3@966.86,5457.84 1008.16,5457.84 v5(1045,5421) ; U4.19@1040.76,3900.68 1087.67,3900.68 1114.97,3873.38 C28.2@1154,3873.38 ; U4.14@1040.76,3999.1 1094.1,3999.1 v5(1116,4021) ; v3(1822.6,5194) U6.11@1860,5194 v3(1860,5216.64) U6.8@1860,5249.12 ; R59.2@2681.01,1747 2681.01,1733.99 2688,1727 R60.2@2738.01,1727 ; R57.2@2681.01,1787 2681.01,1770.99 2685,1767 R58.2@2738.01,1767 ; R54.2@2681.01,1827 2681.01,1809.99 2684,1807 R55.2@2738.01,1807 ; R51.2@2681.01,1867 2681.01,1852.99 2687,1847 R52.2@2738.01,1847 ; U5.5@2707.86,5699.59 2798.41,5699.59 U5.15@2824,5674 ; R50.2@2738.01,1888 2688,1888 2681.01,1894.99 R49.2@2681.01,1908 2681.01,1922.01 2687,1928 R47.2@2738.01,1928 ; R62.2@2833,1612.01 2833,1565 2837.99,1560.01 R63.2@2854,1560.01 2871.01,1560.01 2874,1563 R66.2@2874,1612.01 ; R46.2@2835,2022.99 2833.73,2024.26 2833.73,2072.73 2838.99,2077.99 R45.2@2853,2077.99 2868.01,2077.99 2873.73,2072.27 2873.73,2023.26 R44.2@2874,2022.99 ; R43.2@2893,2077.99 2907.01,2077.99 2915,2070 R42.2@2915,2022.99 ; R67.2@2895,1560.01 2913.01,1560.01 2915,1562 R68.2@2915,1612.01 ; R41.2@2972,2022.99 2972,2073 2976.99,2077.99 R40.2@2992,2077.99 ; R38.2@3012,2022.99 3012,2071.79 3018.2,2077.99 R36.2@3032,2077.99 3049.01,2077.99 3052,2075 R35.1@3052,2022.99
  other v1: 2493,196 2979,196 2063,198 878,200 1641,200 1241,203 1399,499 1664,499 1518,501 883,594 1892,626 1660,627 1399,633 1521,634 1978,729 1399,732 1522,732 1658,734 1521,828 1657,828 1399,829 1522,922 1399,926 1655,927 325,941 883,944 2354,1004 2233,1006 1400,1024 1657,1026 1524,1027 2074,1030 2594,1057 2823,1060 1399,1129 1525,1129 1656,1133 2731,1142 1975,1197 2116,1202 1657,1226 1399,1228 1526,1228 2825,1239 886,1297 325,1300 1655,1320 1525,1322 1399,1323 1972,1357 2304,1377 1398,1429 1522,1430 1655,1430 1958,1463 1464,1502 3482,1552 3621,1554 3703,1558 1929,1588 2218,1616 3421,1621 1538,1636 1898,1655 3536,1659 322,1708 1426,1737 1808,1751 2156,1758 2038,1759 3569,1810 1422,1838 2037,1872 3628,1872 2153,1873 1763,1899 1416,1925 3444,1937 3332,1939 3636,1951 3503,1991 3386,1997 1918,2023 2034,2023 2156,2024 1416,2033 3442,2062 3503,2131 1415,2132 3631,2132 1005,2133 1654,2150 3627,2209 1413,2220 3518,2243 1005,2333 316,2336 780,2336 1413,2339 3516,2343 3627,2345 3515,2440 3625,2441 1426,2442 1730,2462 1941,2474 3627,2531 1542,2532 3518,2532 1749,2560 1905,2588 2121,2614 3517,2620 780,2636 1005,2636 1537,2636 1773,2672 3627,2683 3520,2721 1471,2747 1777,2775 3566,2784 3627,2837 1846,2839 1669,2866 1770,2875 1942,2878 2338,2894 1501,2902 1003,2903 1875,2921 1623,2936 2267,2965 2206,3018 1587,3024 1472,3028 2130,3087 778,3103 1840,3108 1584,3109 1470,3112 1714,3134 2057,3152 1993,3207 3183,3225 3528,3230 1780,3231 1583,3232 1680,3233 1363,3235 1469,3235 1932,3259 1857,3308 1000,3314 1365,3322 1469,3324 1582,3324 1680,3325 1778,3326 1328,3658 3186,3661 3525,3661 1686,3664 2044,3669 2044,4108 2444,4108 2789,4108 3186,4111 3528,4111 3531,4483 3186,4486 2044,4489 2794,4489 2447,4492 3528,4839 2797,4844 2444,4847 2044,4850 3864,5231 300,5386 2597,5386 3856,5608 2442,5900 3069,5906 2000,5908 703,5911 305,5917
  other v2: 1281,3976
  other v3: 2911.54,1725.42 2974.46,1725.42 2852.42,1784.54 2911.54,1784.54 2974.46,1784.54 3033.58,1784.54 2852.42,1847.46 2911.54,1847.46 2974.46,1847.46 3033.58,1847.46 2911.54,1906.58 2974.46,1906.58 259.32,3938.31 298.68,3938.31 259.32,3977.69 298.68,3977.69 682,5049.44 662.32,5077 701.68,5077 682,5104.56 1860,5171.36 1897.4,5194 2794.47,5644.47 2853.53,5644.47 2794.47,5703.53 2853.53,5703.53
  other v4: 1043.63,5474.57 1083,5474.57 1122.37,5474.57 1043.63,5513.94 1083,5513.94 1122.37,5513.94 1043.63,5553.31 1083,5553.31 1122.37,5553.31 1043.63,5592.69 1083,5592.69 1122.37,5592.69 1043.63,5632.06 1083,5632.06 1122.37,5632.06 1043.63,5671.43 1083,5671.43 1122.37,5671.43
  other v5: 2531,3671 812,3976 708,4036 726,4254 1896,4929 1776,5194 2183,5243 1603,5328 784,5429
GPIO3/PWM2: J10.4 U4.33 | length 864.5
  Bottom Layer w10: J10.4@123,3381 167,3425 495,3425 726.79,3656.79 U4.33@726.79,3803.24
GPIO4/SPI(SIMO)/UART(TXD): J10.7 U4.51 | length 641.6
  Signal Layer 1 w10: J10.7@223,3581 465,3823 v2(465,4077)
  Bottom Layer w10: v2@465.84,4077.84 U4.51@511.24,4077.84
GPIO5/SPI(SOMI)/UART(RXD): J10.8 U4.52 | length 720.4
  Signal Layer 1 w10: J10.8@123,3581 171,3629 171,3717 426,3972 426,4087 436,4097 v2(465,4097)
  Bottom Layer w10: v2@465.53,4097.53 U4.52@511.24,4097.53
GPIO6/PWM1/SPI(CS): J10.9 U4.29 | length 724.2
  Bottom Layer w10: J10.9@223,3681 328,3786 519,3786 612,3879 778,3879 805.53,3851.47 U4.29@805.53,3803.24
GPIO7/PWM0: J10.10 U4.23 | length 964.9
  Bottom Layer w10: J10.10@123,3681 261,3819 519,3819 595,3895 896,3895 923.64,3867.36 U4.23@923.64,3803.24
HS: J26.50 R66.1 U1.3 | length 2079.5
  Top Layer w10: v2@2874.1,1658.1 U1.3@2874.1,1682.14
  Signal Layer 1 w6: J26.50@1287,878 1843.58,878 ccw(c1843.58,978) 1914.29,907.29 1947.71,940.71 ccw(c1877,1011.42) 1977,1011.42 1977,1061 cw(c1998.73,1061) 1983.36,1076.36 2027,1120 cw(c2053.56,1093.44) 2053.56,1131 2462.58,1131 ccw(c2462.58,1231) 2533.29,1160.29 2588.71,1215.71 ccw(c2518,1286.42) 2618,1286.42 2618,1326 cw(c2644.56,1326) 2625.78,1344.78 2844.71,1563.71 ccw(c2774,1634.42) 2874,1634.42 v2(2874,1658)
  Bottom Layer w10: R66.1@2874,1637.99 v2(2874,1658)
I2S_CLK: J31.18 U1.13 | length 2858
  Top Layer w10: v2@3076.86,1683.14 U1.13@3076.86,1707.73
  Signal Layer 4 w10: J31.18@617,1989 927,1679 927,1611 1012,1526 3052,1526 3078,1552 v2(3078,1682)
I2S_DA: J31.14 U1.11 | length 2787.8
  Top Layer w10: v2@3031.58,1657.42 U1.11@3031.58,1682.14
  Signal Layer 4 w10: J31.14@617,2189 1079,1727 1357,1727 1526,1558 3011,1558 3032,1579 v2(3032,1657)
I2S_WC: J31.16 U1.12 | length 2786.4
  Top Layer w10: v2@3051.27,1657.27 U1.12@3051.27,1682.14
  Signal Layer 4 w10: J31.16@617,2089 1076,1630 1348,1630 1436,1542 3027,1542 3051,1566 v2(3051,1657)
IDX: C2.1 J2.1 S2.1 S2.2 S2.3 S2.4 S2.5 S2.6 S2.7 S2.8 U1.6 | length 2690.3
  Top Layer w10: v2(2933,1658) 2933,1681.98 U1.6@2933.16,1682.14
  Top Layer w30: S2.1@3014,401.71 S2.2@3114,401.71 S2.3@3214,401.71 S2.4@3314,401.71 S2.5@3414,401.71 S2.6@3514,401.71 S2.7@3614,401.71 S2.8@3714,401.71 3836.71,401.71 3898,463 J2.1@3898,574 C2.1@3985.62,574
  Signal Layer 3 w10: v2(2933,1658) 2933,1613 3549,997 3549,796 3771,574 J2.1@3898,574
INTB_R: R48.1 R53.1 U1.31 | length 1057.3
  Top Layer w10: R48.1@2833.62,2692 v2@2833.62,2731.62 ; U1.31@2933.16,1949.86 v2@2933.16,1974.84
  Top Layer w20: R53.1@2833.62,2653 R48.1@2833.62,2692
  Bottom Layer w10: v2(2834,2732) 2744,2732 2711,2699 2711,2509.37 2884,2336.37 2884,2173 2934.27,2122.73 2934.27,1976.27 v2(2933,1975)
L10_N: L11.1 P1.1 | length 1298.6
  Signal Layer 4 w4.5: v2(3480,1827.25) ccw(c3484.83,1832.08) 3484.83,1825.25 3509.57,1825.25 ccw(c3509.57,1852.43) 3528.79,1833.21 3573.01,1877.43 ccw(c3540.44,1910) 3586.5,1910 3586.5,2692.55 cw(c3598.45,2692.55) 3590,2701 3689.45,2800.45 cw(c3727,2762.89) 3727,2816 cw(c3727,2774.96) 3756.02,2803.98 3802.03,2757.97 cw(c3762.68,2718.63) P1.1@3818.32,2718.63
  Bottom Layer w5.5: L11.1@3449.46,1817.28 3455.84,1817.28 ccw(c3455.84,1851.31) 3479.9,1827.25 v2(3480,1827.25)
L10_P: L11.4 P1.3 | length 1356.3
  Signal Layer 4 w4.5: v2(3480,1842.75) cw(c3484.83,1837.92) 3484.83,1844.75 3509.57,1844.75 ccw(c3509.57,1852.43) 3515,1847 3559.22,1891.22 ccw(c3540.44,1910) 3567,1910 3567,2692.55 cw(c3598.45,2692.55) 3576.21,2714.79 3675.65,2814.23 cw(c3727,2762.89) 3727,2835.5 3817.51,2835.5 cw(c3817.51,2735.5) 3888.22,2806.21 P1.3@3897.06,2797.37 P1.3@3884.98,2785.29
  Bottom Layer w5.5: L11.4@3449.46,1852.72 3455.84,1852.72 cw(c3455.84,1818.69) 3479.9,1842.75 v2(3480,1842.75)
MODE_SEL: C1.1 J1.1 S1.1 S1.2 S1.3 S1.4 S1.5 S1.6 S1.7 S1.8 U1.24 | length 2839.7
  Top Layer w10: S1.8@2767,399.71 v2@2833.29,399.71 ; U1.24@3076.86,1924.27 v2@3076.86,1953.86
  Top Layer w30: C1.1@1911.62,527 1911.62,406.38 J1.1@1917,401 1918.29,399.71 S1.1@2067,399.71 S1.2@2167,399.71 S1.3@2267,399.71 S1.4@2367,399.71 S1.5@2467,399.71 S1.6@2567,399.71 S1.7@2667,399.71 S1.8@2767,399.71
  Signal Layer 2 w10: v2(2835,400) 2920,400 3150,630 3150,1654 3078,1726 v2(3078,1955)
NetC3_1: C3.1 J3.1 R31.1 R64.2 S3.1 S4.4 | length 587.5
  Top Layer w20: S4.4@2580.38,2984.38 2580.38,2870 C3.1@2677,2870 2781.95,2870 ; 2783,2871.05 J3.1@2953.95,2871.05 ; J3.1@2959.38,2865.62 R64.2@3060,2865.62
NetC4_1: C4.1 J5.1 L1.1 R33.2 | length 548.9
  Bottom Layer w30: J5.1@3063,1177 3188,1177 3229,1218 C4.1@3351,1218 3414,1218 3440,1192 L1.1@3440,1159.62 R33.2@3551.76,1159.62
NetC5_1: C5.1 J5.2 X1.4 | length 968.1
  Signal Layer 4 w20: J5.2@2963,1177 3102,1316 3520,1316 v2(3658,1454)
  Bottom Layer w20: v2@3656.5,1455.5 C5.1@3656.5,1509
  Bottom Layer w30: X1.4@3551,1509.68 C5.1@3655.83,1509.68
NetC8_1: C8.1 M1.1 | length 329
  Top Layer w30: C8.1@206,6008 M1.1@206,6337
NetC9_1: C9.1 M2.1 | length 297
  Top Layer w30: C9.1@3897,6030 M2.1@3897,6327
NetC10_1: C10.1 M3.1 | length 255
  Top Layer w30: C10.1@208,2602 M3.1@208,2857
NetC11_1: C11.1 M4.1 | length 306
  Top Layer w30: M4.1@3895,3909 C11.1@3895,4215
NetC12_1: C12.1 M5.1 | length 275
  Top Layer w30: C12.1@3614,195 M5.1@3889,195
NetC13_1: C13.1 M6.1 | length 268
  Top Layer w30: M6.1@206,196 C13.1@206,464
NetC15_1: C15.1 L2.2 U2.5 U2.8 | length 400.7
  Top Layer w10: U2.5@334.12,3919.61 369.61,3919.61 413.62,3963.62 C15.1@478,3963.62 ; U2.8@334.12,3996.39 469.61,3996.39 478,3988 C15.1@478,3963.62 ; L2.2@544.88,3963.62 C15.1@478,3963.62
NetC16_1: C16.1 R79.1 U2.1 | length 204.2
  Top Layer w10: C16.1@111,4038.87 161.87,4038.87 196.39,4073.39 223.88,4073.39 U2.1@223.88,3996.39
NetC17_1: C17.1 U2.3 | length 112.5
  Top Layer w10: C17.1@116,3934 170,3934 181.2,3945.2 U2.3@223.88,3945.2
NetC18_2: C18.2 F1.2 J7.1 U3.6 | length 296
  Top Layer w10: J7.1@305.36,4498.99 430.13,4498.99 F1.2@430.13,4574.5 ; F1.2@438.64,4583 C18.2@438.64,4678.74
NetC19_2: C19.2 R85.2 U4.70 Y1.2 | length 719.9
  Bottom Layer w10: U4.70@766.16,4332.76 766.16,4375.16 795.62,4404.62 R85.2@795.62,4440 795.62,4533.62 829.63,4567.63 871.82,4567.63 872.19,4568 895.95,4568 945.95,4618 Y1.2@1133.01,4618 C19.2@1133.01,4752.5
NetC21_2: C21.2 R85.1 U4.69 Y1.1 | length 410.8
  Bottom Layer w10: U4.69@746.47,4332.76 Y1.1@746.47,4605.48 ; C21.2@756.5,4755 756.5,4620.5 Y1.1@758.99,4618
NetC23_2: C23.2 J9.11 R86.2 U4.76 | length 831.8
  Bottom Layer w10: U4.76@884.27,4332.76 884.27,4377.76 898.51,4392 1119,4392 1177.5,4333.5 C23.2@1258,4333.5 R86.2@1308.13,4333.5 ; R86.2@1309,4332.62 1365.38,4332.62 1430,4268 1430,4223 J9.11@1529,4124
NetC24_1: C24.1 U4.9 | length 103.4
  Bottom Layer w10: U4.9@1040.76,4097.53 C24.1@1144.15,4097.53
NetC29_1: C29.1 U4.20 | length 156.3
  Bottom Layer w10: C29.1@1043,3722.5 U4.20@1043,3878.76
NetC30_1: C30.1 C31.2 R90.2 R91.1 U5.2 | length 247.4
  Bottom Layer w10: R91.1@2459,5621.38 U5.2@2706.42,5621.38
NetC32_1: C32.1 C33.1 C34.1 J11.2 R93.1 U5.13 U5.14 | length 621.3
  Bottom Layer w10: R93.1@2752.62,5809 2838,5809 2894,5753 2894,5636 2907.18,5622.82 U5.13@2940.14,5622.82 2942.38,5620.58 C34.1@2942.38,5408 ; J11.2@2944,5334 C34.1@2944,5406.38
NetC46_1: C46.1 U5.12 | length 134.9
  Bottom Layer w10: U5.12@2940.14,5648.41 C46.1@3075.03,5648.41
NetC46_2: C46.2 L6.2 U5.10 U5.11 | length 1348.3
  Bottom Layer w30: L6.2@2768.17,5308 2768.17,5144.83 2821,5092 3026,5092 3074,5140 3074,5503 3180,5609 3180,5665 3148.38,5696.62 C46.2@3076,5696.62 3015.62,5696.62 3007,5688 2928,5688
NetC57_1: C57.1 U5.4 | length 78.2
  Top Layer w10: C57.1@2629.62,5674 v2(2663,5674)
  Bottom Layer w10: v2(2663,5674) U5.4@2707.86,5674
NetC58_1: C58.1 R92.2 U5.3 | length 150.4
  Bottom Layer w10: C58.1@2579,5677.5 R92.2@2624.87,5677.5 ; R92.2@2627,5675.38 2627,5654 2632.59,5648.41 U5.3@2707.86,5648.41
NetC60_1: C60.1 C61.1 L8.2 R94.1 R96.1 U6.4 | length 1542
  Bottom Layer w10: L8.2@1684.54,5247 1684,5247.54 R94.1@1684,5692.38 1623.38,5692.38 1519.93,5588.93 C61.1@1519.93,5063 1521.43,5061.5 C60.1@1606,5061.5 1704.5,5061.5 R96.1@1705,5062 1781.37,5062 1840.32,5120.94 U6.4@1840.32,5138.88
NetC60_2: C60.2 R96.2 R98.2 U6.5 | length 310
  Bottom Layer w10: R98.2@1605,5213.5 1605,5125.5 C60.2@1606,5124.5 1639.5,5124.5 1653.88,5138.88 U6.5@1820.63,5138.88
NetC65_1: C65.1 C66.1 L10.2 R99.1 R101.1 | length 343.6
  Bottom Layer w10: L10.2@2077.34,5237 2077.34,5062.84 2183.77,5062.84 R99.1@2183.77,4999.85
NetC65_2: C65.2 R101.2 R104.2 U6.1 | length 243.6
  Bottom Layer w10: U6.1@1899.37,5138.88 2007.62,5138.88 C65.2@2011.5,5135 2013.5,5133 R101.2@2013.5,5062 R104.2@2013.5,5006
NetC71_1: C71.1 R105.1 R106.2 U7.5 | length 262.5
  Bottom Layer w10: U7.5@746.96,5124.24 785.24,5124.24 797.38,5136.38 R105.1@817,5136.38 ; R106.2@817,5079.62 817,5133.62 818.38,5135 C71.1@949.91,5135
NetC72_2: C72.2 C73.1 C76.2 C77.1 J20.1 J22.2 U8.5 U8.6 U8.11 U8.12 | length 731.6
  Bottom Layer w10: J22.2@711,5513 782.38,5513 C73.1@783,5513.62 784.38,5515 C72.2@842,5515 892,5515 897.98,5509.02 U8.5@966.86,5509.02 U8.6@966.86,5534.61 ; J20.1@711,5670 788,5670 C76.2@790,5672 794.38,5676.38 C77.1@865,5676.38 912.62,5676.38 926.43,5662.57 U8.11@966.86,5662.57 U8.12@966.86,5688.16
  Bottom Layer w30: J22.2@711,5513 J20.1@711,5670
NetC74_2: C74.2 C75.1 R109.1 R111.1 U8.23 U8.24 | length 409.4
  Bottom Layer w10: U8.24@1199.14,5509.02 1249.98,5509.02 1258.62,5500.38 1319.62,5500.38 R109.1@1319.62,5436 1319.62,5370.62 1296.12,5347.12 1253.5,5347.12 R111.1@1253.5,5293
  Bottom Layer w20: U8.24@1199.14,5509.02 U8.23@1199.14,5534.61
